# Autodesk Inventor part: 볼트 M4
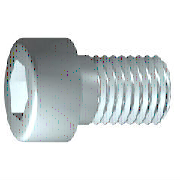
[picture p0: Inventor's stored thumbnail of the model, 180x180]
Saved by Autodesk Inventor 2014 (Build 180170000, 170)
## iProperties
IsCustomPart: 1
Created: 2012-02
Part Number: 볼트 M4
Material: 스테인리스강
Description: 6각 소켓 머리 캡 나사
Document SubType Name: Modeling
Standard: ISO 4762
Designer: mduedu
Standard Revision: Fourth edition 2004-03-01
Standards Organization: ISO
Language: ko-KR
Size Designation: M4 x 10
Categories: <MemberInstance><Categories><Category DisplayName="조임쇠" InternalName="e4da775c-781d-43d5-af7c-5136215cf5a6" Mnemonic="FSTN"><Category DisplayName="볼트" InternalN
Density: 8.08 g/cm^3
Appearance: 반광택
Mass: 2.0939 g
Surface Area: 3.06255 cm^2
Volume: 0.259146 cm^3
Author: mduedu
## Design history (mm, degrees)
sketch "스케치1"
  geometry: L1 (-1, 0)-(10, 0); L2 (10, 0)-(10, 2); L3 (10, 2)-(1.75, 2); L4 (1.75, 2)-(1.32, 2); L5 (1.32, 2)-(0, 2); L6 (0, 2)-(0, 3.5); L7 (0, 3.5)-(-4, 3.5); L8 (-4, 3.5)-(-4, 1.732); L9 (-4, 1.732)-(-2, 1.732); L10 (-2, 1.732)-(-1, 0); L11 (-6.8, 0)-(12.8, 0) reference; L12 (0, -0.7)-(0, 4.2) reference; L13 (1.75, 2)-(0, 2)
  constraints: 22 end point, 6 parallel, 2 collinear, 2 perpendicular, 1 horizontal, 1 point on line
  dimensions: "d1" = 8.25 distance from line of L3.end L2 (= GEL); "d2" = 0.42952 distance of L4.end L3.end (computed from GAL); "d3" = 4 distance between parallel lines of L8 L6 (= KOH); "d4" = 2 distance of L8.end L9.end (= INTI); "d5" = 60 deg angle of L10 L1; "d6" = 4 diameter of L3 L1 (= GD); "d7" = 4 diameter of L5 L1 (= BDM); "d8" = 3.4641 diameter of L9 L1 (= 1.1547 x SW); "d9" = 7 diameter of L7 L1 (= KOD); "d26" = 10 distance between parallel lines of L12 L2 (= NLG)
revolve "본체" sketch "스케치1" stored, may be unused: angle "d10" = 90 deg
sketch "스케치2"
  geometry: L1 (0, -4.9)-(0, 4.9) reference; L2 (-4.9, 0)-(4.9, 0) reference; L3 (1.732, 0)-(0.866, -1.5); L4 (0.866, -1.5)-(-0.866, -1.5); L5 (-0.866, -1.5)-(-1.732, 0); L6 (-1.732, 0)-(-0.866, 1.5); L7 (-0.866, 1.5)-(0.866, 1.5); L8 (0.866, 1.5)-(1.732, 0); 2 further points
  constraints: 12 end point, 1 coincident, 1 horizontal alignment, 1 point on line, 12 other
extrude "슬롯" join sketch "스케치2" stored distance "d11" = 10; taper "d12" = 0 deg
workplane "Work Plane1"
body "Solid1"
fillet "모깎기1" dims "d17" = 0.4 (= RR)
feature "스레드" dims "d13" = 8.25 (= GEL), "d14" = 0
chamfer "모따기1" distance "d15" = 0.42941 (= -0.5 x SPD + 0.5 x GD); stored, may be unused: second distance "d16" = 0.42941 (= GUL), angle "d27" = 45 deg
other parameters: "GD" = 4 [user parameter; used in 2 equation terms], "NLG" = 10 [user parameter; used in 1 equation term], "GEL" = 8.25 [user parameter; used in 2 equation terms], "KOD" = 7 [user parameter; used in 1 equation term], "KOH" = 4 [user parameter; used in 1 equation term], "INTI" = 2 [user parameter; used in 1 equation term], "GAL" = 0.42941 (= 0.61345 x PTC) [user parameter; used in 1 equation term], "GUL" = 0.42941 (= 0.61345 x PTC) [user parameter; used in 1 equation term], "BDM" = 4 (= NND) [user parameter; used in 1 equation term], "SW" = 3 [user parameter; used in 2 equation terms], "RR" = 0.4 [user parameter; used in 1 equation term], "SPD" = 3.14117 (= NND - 1.2269 x PTC) [user parameter; used in 1 equation term], "d19" = 0, "d28" = 0, "d29" = 0, "R" = 0.1 [user parameter], "TOA" = 30 deg [user parameter], "GD1" = 3.14117 (= THREADDIA - 1.2269 x PTC) [user parameter], "THREADDIA" = 4 [user parameter; used in 1 equation term], "FAWI" = 45 deg [user parameter], "TPU" = 14.28571 (computed from PTC) [user parameter], "PTC" = 0.7 [user parameter; used in 5 equation terms], "NND" = 4 [user parameter; used in 2 equation terms], "E0" = 3.465 (= 1.155 x SW) [user parameter]
